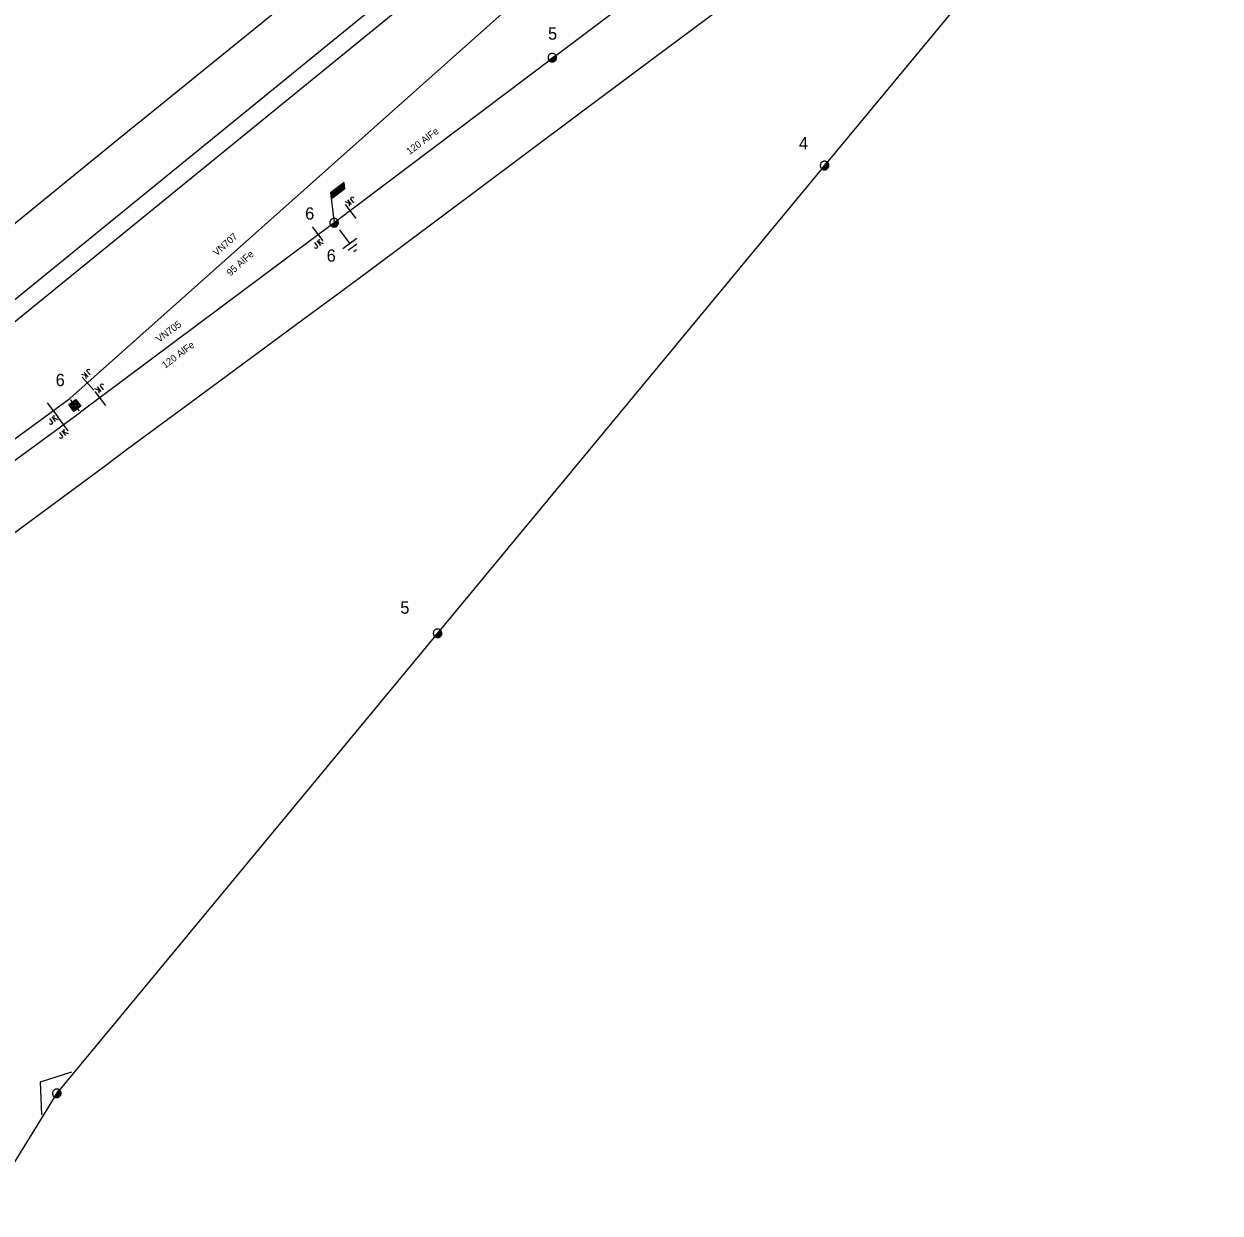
# Model space of a CAD drawing. Extents: x -545588 to -543214, y -1196037 to -1194452.
# Drawn here: x -545402.3 to -545231.7, y -1195194.1 to -1195024.5 of the extents above; entities that cross this region are included whole.
import ezdxf

# ---------------------------------------------------------------- set-up
doc = ezdxf.new("R2010")
doc.units = 0
for name, color, linetype in [('Default', 7, 'Continuous'), ('Vrstva 1', 7, 'Continuous'), ('Vrstva 11', 7, 'Continuous'), ('Vrstva 12', 7, 'Continuous'), ('Vrstva 13', 7, 'Continuous'), ('Vrstva 14', 7, 'Continuous'), ('Vrstva 15', 7, 'Continuous'), ('Vrstva 18', 7, 'Continuous'), ('Vrstva 2', 7, 'Continuous'), ('Vrstva 3', 7, 'Continuous'), ('Vrstva 35', 7, 'Continuous')]:
    doc.layers.add(name, color=color, linetype=linetype)

# ---------------------------------------------------------------- blocks, each defined once
blk = doc.blocks.new('VN840')
at = {"layer": 'Vrstva 15'}
for points in [[(-0.01, 1.41), (-0.01, -1.09)], [(-1.51, -1.24), (-1.51, -1.15)], [(-1.48, -1.35), (-1.51, -1.24)], [(-1.33, -1.42), (-1.48, -1.35)], [(-1.27, -1.42), (-1.33, -1.42)], [(-1.13, -1.35), (-1.27, -1.42)], [(-1.09, -1.24), (-1.13, -1.35)], [(-1.09, -0.59), (-1.09, -1.24)], [(-0.68, -0.59), (-0.68, -1.42)], [(-0.68, -1.11), (-0.27, -0.59)], [(-0.54, -0.94), (-0.2, -1.42)]]:
    blk.add_lwpolyline(points, dxfattribs=at)
blk = doc.blocks.new('VN860')
at = {"layer": 'Vrstva 15'}
for points in [[(-3.74, 0), (0.01, 2.82)], [(0.01, 2.82), (3.76, 0)]]:
    blk.add_lwpolyline(points, dxfattribs=at)
blk = doc.blocks.new('VN440')
at = {"layer": 'Vrstva 2'}
for points in [[(1.22, 0), (1.21, 0.13), (1.19, 0.25), (1.16, 0.38), (1.11, 0.5), (1.05, 0.61), (0.98, 0.72), (0.9, 0.82), (0.81, 0.91), (0.71, 0.99), (0.6, 1.06), (0.49, 1.12), (0.37, 1.16), (0.25, 1.2), (0.12, 1.22), (-0.01, 1.22), (-0.14, 1.22), (-0.26, 1.2), (-0.39, 1.16), (-0.51, 1.12), (-0.62, 1.06), (-0.73, 0.99), (-0.83, 0.91), (-0.92, 0.82), (-1, 0.72), (-1.07, 0.61), (-1.13, 0.5), (-1.18, 0.38), (-1.21, 0.25), (-1.23, 0.13), (-1.24, 0), (-1.23, -0.13), (-1.21, -0.26), (-1.18, -0.38), (-1.13, -0.5), (-1.07, -0.62), (-1, -0.73), (-0.92, -0.83), (-0.83, -0.92), (-0.73, -1), (-0.62, -1.07), (-0.51, -1.13), (-0.39, -1.17), (-0.26, -1.2), (-0.14, -1.23), (-0.01, -1.23), (0.12, -1.23), (0.25, -1.2), (0.37, -1.17), (0.49, -1.13), (0.6, -1.07), (0.71, -1), (0.81, -0.92), (0.9, -0.83), (0.98, -0.73), (1.05, -0.62), (1.11, -0.5), (1.16, -0.38), (1.19, -0.26), (1.21, -0.13), (1.22, 0)], [(-1.24, 0), (1.22, 0)], [(-1.18, -0.34), (1.1, -0.34)], [(-1.01, -0.63), (0.97, -0.63)], [(-0.74, -0.92), (0.68, -0.92)]]:
    blk.add_lwpolyline(points, dxfattribs=at)
blk = doc.blocks.new('VN810')
at = {"layer": 'Vrstva 14'}
for points in [[(0, -1.25), (0, -3.75)], [(1.25, -3.75), (-1.25, -3.75)], [(0.77, -4.37), (-0.8, -4.37)], [(0, -5), (-0.25, -5)], [(0.27, -5), (0, -5)]]:
    blk.add_lwpolyline(points, dxfattribs=at)
blk = doc.blocks.new('VN001')
at = {"layer": 'Default'}
for p, q in [((1.96, 3.43), (4.37, 3.43)), ((1.99, 3.48), (4.4, 3.48)), ((2.02, 3.53), (4.43, 3.53)), ((2.05, 3.58), (4.46, 3.58)), ((2.07, 3.63), (4.49, 3.63)), ((2.1, 3.68), (4.52, 3.68)), ((2.13, 3.73), (2.54, 3.73)), ((1.73, 3.03), (4.14, 3.03)), ((1.76, 3.08), (4.17, 3.08)), ((1.79, 3.13), (4.2, 3.13)), ((1.82, 3.18), (4.23, 3.18)), ((1.85, 3.23), (4.26, 3.23)), ((1.87, 3.28), (4.29, 3.28)), ((1.9, 3.33), (4.32, 3.33)), ((1.93, 3.38), (4.35, 3.38))]:
    blk.add_line(p, q, dxfattribs=at)
blk.add_lwpolyline([(2.13, 3.73), (0, 0)], dxfattribs=at)
blk.add_lwpolyline([(4.55, 3.73), (2.13, 3.73), (1.7, 2.98), (4.12, 2.99)], close=True, dxfattribs=at)
blk = doc.blocks.new('VN470')
at = {"layer": 'Vrstva 2'}
for points in [[(-1.23, 1.22), (1.23, 1.22)], [(-1.23, -1.23), (-1.23, 1.22)], [(-0.92, 0.9), (0.92, 0.9)], [(-0.92, -0.95), (-0.92, 0.9)], [(-0.61, 0.61), (0.61, 0.61)], [(-0.61, -0.62), (-0.61, 0.61)], [(-0.31, -0.27), (-0.31, 0.34)], [(-0.31, 0.34), (0.31, 0.34)], [(0, 1.22), (0, 1.97)], [(0.31, 0.34), (0.31, -0.27)], [(0.61, 0.61), (0.61, -0.62)], [(0.92, 0.9), (0.92, -0.95)], [(1.23, 1.22), (1.23, -1.23)], [(1.23, -1.23), (-1.23, -1.23)], [(0.92, -0.95), (-0.92, -0.95)], [(0.61, -0.62), (-0.61, -0.62)], [(0.31, -0.27), (-0.31, -0.27)], [(0, -1.23), (0, -1.98)]]:
    blk.add_lwpolyline(points, dxfattribs=at)

msp = doc.modelspace()

# ---------------------------------------------------------------- linework, layer by layer
at = {"layer": 'Vrstva 1'}
for points in [[(-545395.75, -1195077.92), (-545332.4, -1195021.48), (-545278.54, -1194980.38), (-545246.31, -1194956.61)], [(-545240.53, -1194964.58), (-545269.49, -1194986.16), (-545326.84, -1195029.29), (-545358.05, -1195052.83)], [(-545290.64, -1194971.78), (-545405.11, -1195065.07), (-545495.54, -1195139.14), (-545571.44, -1195160.65)], [(-545289.27, -1194973.82), (-545403.67, -1195067.08), (-545494.32, -1195141.28), (-545571.32, -1195163.18)], [(-545231.73, -1194976.58), (-545288.13, -1195044.67), (-545343.3, -1195111.41), (-545397.6, -1195177.04), (-545441.95, -1195249.1), (-545485.78, -1195319.69), (-545525.23, -1195383.69), (-545557.58, -1195435.71)], [(-545358.05, -1195052.83), (-545394.22, -1195079.84)], [(-545570.96, -1195170.23), (-545491.96, -1195148.44), (-545395.75, -1195077.92)], [(-545570.84, -1195172.71), (-545490.55, -1195150.49), (-545394.22, -1195079.84)]]:
    msp.add_lwpolyline(points, dxfattribs=at)
at = {"layer": 'Vrstva 35'}
for points in [[(-545289.91, -1195012.5), (-545312.5, -1195029.39), (-545323.35, -1195037.5), (-545337.5, -1195048.08), (-545352.95, -1195059.63), (-545356.83, -1195062.5), (-545362.5, -1195066.69), (-545378.52, -1195078.52), (-545387.5, -1195085.16), (-545390.67, -1195087.5), (-545412.5, -1195103.63)], [(-545410.48, -1195058.49), (-545399.88, -1195049.88), (-545387.5, -1195039.82), (-545384.64, -1195037.5), (-545362.5, -1195019.51)]]:
    msp.add_lwpolyline(points, dxfattribs=at)

# ---------------------------------------------------------------- block references
at = {"layer": 'Vrstva 11', "rotation": 36.748177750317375}
msp.add_blockref('VN001', (-545358.05, -1195052.83), dxfattribs=at)
at = {"layer": 'Vrstva 13'}
for name, p, xscale, yscale, rotation in [('VN440', (-545326.94, -1195029.28), 0.5, 0.5000000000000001, 37.1260583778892), ('VN440', (-545288.13, -1195044.67), 0.49999999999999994, 0.5000000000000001, 50.42141944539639), ('VN440', (-545358.05, -1195052.83), 0.5, 0.5, 36.74807496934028), ('VN470', (-545395.02, -1195078.9), 0.5, 0.5, -143.35134994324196), ('VN440', (-545343.3, -1195111.41), 0.5, 0.5, 50.396755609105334), ('VN440', (-545397.6, -1195177.04), 0.5, 0.5, 58.389286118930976)]:
    msp.add_blockref(name, p, dxfattribs=dict(at, xscale=xscale, yscale=yscale, rotation=rotation))
at = {"layer": 'Vrstva 15', "rotation": 36.748008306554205}
msp.add_blockref('VN810', (-545358.05, -1195052.83), dxfattribs=at)
at = {"layer": 'Vrstva 18'}
for name, p, rotation in [('VN840', (-545355.78, -1195051.12), -142.97507770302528), ('VN840', (-545360.32, -1195054.53), 36.74898342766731), ('VN840', (-545393.26, -1195075.7), -138.30348056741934), ('VN840', (-545391.47, -1195077.79), -143.2516889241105), ('VN840', (-545398.11, -1195079.65), 36.24423325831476), ('VN840', (-545396.67, -1195081.64), 36.256725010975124), ('VN860', (-545397.6, -1195177.04), 55.01536398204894)]:
    msp.add_blockref(name, p, dxfattribs=dict(at, rotation=rotation))

# ---------------------------------------------------------------- texts
at = {"layer": 'Vrstva 12'}
msp.add_text('6', height=1.75, dxfattribs=at).set_placement((-545359.12, -1195058.39))
at = {"layer": 'Vrstva 14'}
for s, p in [('5', (-545327.56, -1195026.72)), ('4', (-545291.79, -1195042.37)), ('6', (-545362.19, -1195052.39)), ('6', (-545397.76, -1195076.14)), ('5', (-545348.62, -1195108.62))]:
    msp.add_text(s, height=1.75, dxfattribs=at).set_placement(p)
at = {"layer": 'Vrstva 2'}
for s, rotation, p in [('120 AlFe', 37.025, (-545347.29, -1195043.19)), ('95 AlFe', 41.697, (-545372.85, -1195060.51)), ('120 AlFe', 36.748, (-545382.15, -1195073.68))]:
    msp.add_text(s, height=1, rotation=rotation, dxfattribs=at).set_placement(p)
at = {"layer": 'Vrstva 3'}
for s, rotation, p in [('VN707', 41.697, (-545374.79, -1195057.65)), ('VN705', 36.748, (-545382.99, -1195069.98))]:
    msp.add_text(s, height=1, rotation=rotation, dxfattribs=at).set_placement(p)

doc.saveas('drawing.dxf')
